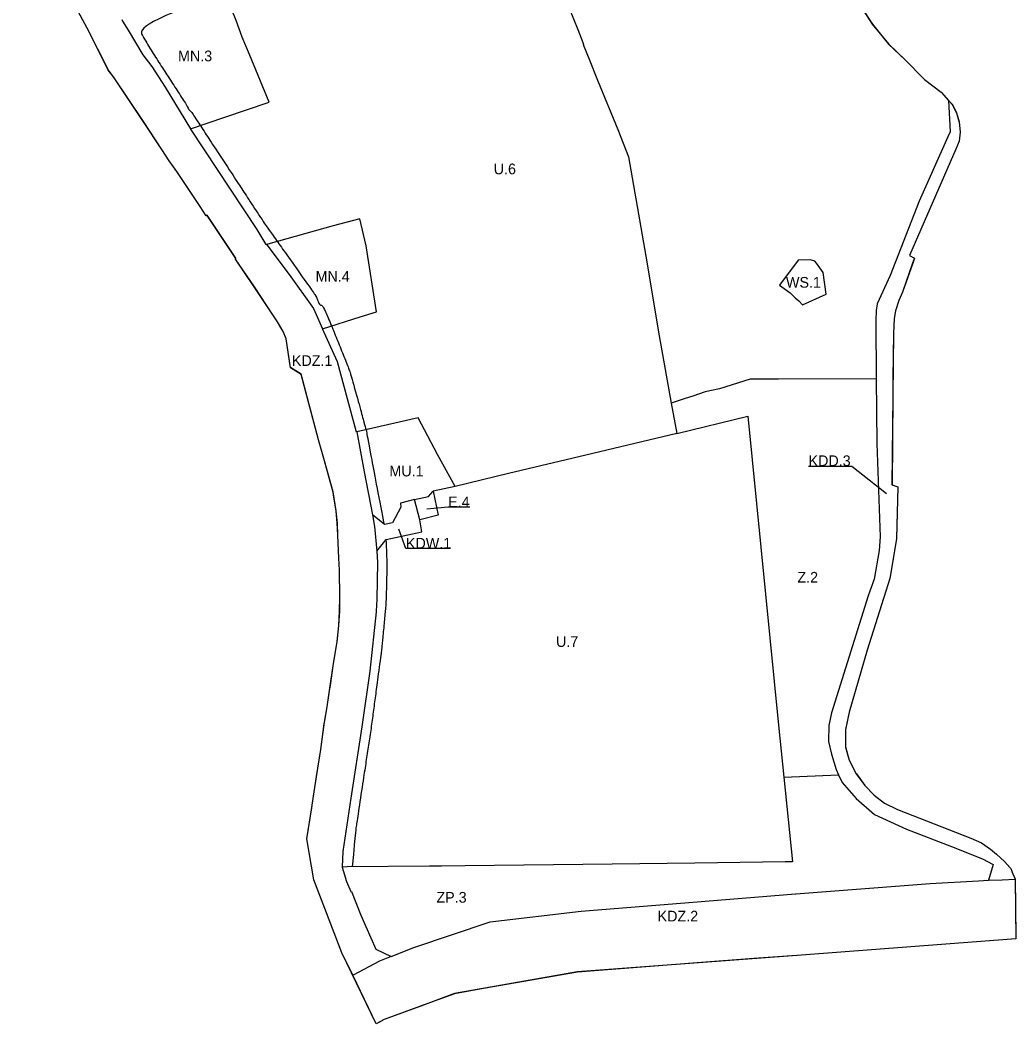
# Model space of a CAD drawing. Extents: x 7426917 to 7427860, y 5549047 to 5550050.
# Drawn here: x 7427266.6 to 7427685.5, y 5549047.4 to 5549469.9 of the extents above; entities that cross this region are included whole.
import ezdxf

# ---------------------------------------------------------------- set-up
doc = ezdxf.new("R2010")
doc.units = 0
for name, color, linetype in [('UG_WSCH_granica obszaru objętego planem', 7, 'Continuous'), ('UG_WSCH_linie rozgraniczające tereny', 7, 'Continuous'), ('UG_WSCH_linie rozgraniczające tereny_OPISY', 7, 'Continuous'), ('UG_WSCH_nieprzekraczalne linie zabudowy', 7, 'Continuous')]:
    doc.layers.add(name, color=color, linetype=linetype)

msp = doc.modelspace()

# ---------------------------------------------------------------- linework, layer by layer
at = {"layer": 'UG_WSCH_granica obszaru objętego planem'}
for p, q in [((7427303.71, 5549448.83), (7427294.86, 5549466.52)), ((7427305.89, 5549446.11), (7427303.71, 5549448.83)), ((7427318.5, 5549427.19), (7427305.89, 5549446.11)), ((7427326.25, 5549415.45), (7427318.5, 5549427.19)), ((7427329.32, 5549410.72), (7427326.25, 5549415.45)), ((7427331.18, 5549408.21), (7427329.32, 5549410.72)), ((7427344.92, 5549387.57), (7427342.4, 5549391.44)), ((7427357.25, 5549369.27), (7427357.31, 5549369.67)), ((7427365.12, 5549357.73), (7427357.25, 5549369.27)), ((7427374.86, 5549342.9), (7427365.12, 5549357.73)), ((7427380.29, 5549323.65), (7427378.49, 5549335.83)), ((7427394.66, 5549284.38), (7427392.05, 5549293.25)), ((7427398.23, 5549271.32), (7427394.66, 5549284.38)), ((7427399.55, 5549263.32), (7427398.23, 5549271.32)), ((7427401.02, 5549227.11), (7427400.89, 5549238.44)), ((7427401.01, 5549221.15), (7427401.02, 5549227.11)), ((7427400.6, 5549215.14), (7427401.01, 5549221.15)), ((7427399.97, 5549208.33), (7427400.6, 5549215.14)), ((7427398.44, 5549199.1), (7427399.97, 5549208.33)), ((7427396.79, 5549187.73), (7427398.44, 5549199.1)), ((7427395.7, 5549180.89), (7427396.79, 5549187.73)), ((7427394.65, 5549174.39), (7427395.7, 5549180.89)), ((7427393.05, 5549162.97), (7427394.65, 5549174.39)), ((7427391.32, 5549151.5), (7427393.05, 5549162.97)), ((7427390.28, 5549145.09), (7427391.32, 5549151.5)), ((7427389.3, 5549138.45), (7427390.28, 5549145.09)), ((7427387.18, 5549125.33), (7427389.3, 5549138.45)), ((7427630.13, 5549140.33), (7427635.71, 5549137.71)), ((7427390.15, 5549108.13), (7427387.18, 5549125.33)), ((7427683.29, 5549112.82), (7427684.22, 5549110.61)), ((7427401.94, 5549077.31), (7427390.15, 5549108.13)), ((7427684.22, 5549110.61), (7427685.15, 5549108.41)), ((7427685.15, 5549108.41), (7427685.45, 5549083.26)), ((7427685.45, 5549083.26), (7427595.26, 5549076.42)), ((7427416.4, 5549047.44), (7427401.94, 5549077.31)), ((7427595.26, 5549076.42), (7427501.08, 5549069.29)), ((7427439.22, 5549056.45), (7427419.77, 5549049.32)), ((7427419.77, 5549049.32), (7427416.4, 5549047.44))]:
    msp.add_line(p, q, dxfattribs=at)
for points in [[(7427294.86, 5549466.52), (7427282.38, 5549489.77), (7427278.39, 5549499.07), (7427266.6, 5549528.2)], [(7427620.19, 5549475.66), (7427625.06, 5549468.24), (7427631.86, 5549459.88), (7427638.82, 5549453.22), (7427647.03, 5549444.9), (7427654.02, 5549439.6), (7427658.71, 5549434.38), (7427660.48, 5549430.85), (7427661.64, 5549427.04), (7427662.02, 5549422.78), (7427661.56, 5549418.94), (7427660.19, 5549415.6), (7427640.63, 5549370.91), (7427642.77, 5549369.72), (7427642.02, 5549367.59), (7427637.71, 5549355.45), (7427636.16, 5549351.94), (7427634.78, 5549347.6), (7427634.26, 5549344.27), (7427633.98, 5549338.16), (7427633.63, 5549311.85), (7427633.33, 5549274.36), (7427635.77, 5549273.51), (7427635.25, 5549251.68), (7427632.43, 5549234.9), (7427622.9, 5549204.73), (7427615.37, 5549178.61), (7427613.76, 5549171.29), (7427613.73, 5549163.98), (7427615.29, 5549158.39), (7427618.32, 5549152.71)], [(7427342.4, 5549391.44), (7427332.51, 5549406.21), (7427331.18, 5549408.21)], [(7427357.31, 5549369.67), (7427345.31, 5549387.76), (7427344.92, 5549387.57)], [(7427378.49, 5549335.83), (7427377.23, 5549338.89), (7427374.86, 5549342.9)], [(7427392.05, 5549293.25), (7427384.84, 5549320.85), (7427380.29, 5549323.65)], [(7427400.26, 5549253.11), (7427400.03, 5549258.25), (7427399.55, 5549263.32)], [(7427400.89, 5549238.44), (7427400.69, 5549243.41), (7427400.26, 5549253.11)], [(7427618.32, 5549152.71), (7427618.33, 5549152.68), (7427621.89, 5549147.82)], [(7427621.89, 5549147.82), (7427625.79, 5549143.76), (7427630.13, 5549140.33)], [(7427635.71, 5549137.71), (7427666.46, 5549125.62), (7427670.99, 5549123.63), (7427674.8, 5549120.98), (7427677.28, 5549118.83)], [(7427677.28, 5549118.83), (7427680.71, 5549115.84), (7427682.96, 5549113.2), (7427683.29, 5549112.82)], [(7427501.08, 5549069.29), (7427449.35, 5549060.17), (7427439.22, 5549056.45)]]:
    msp.add_lwpolyline(points, dxfattribs=at)
at = {"layer": 'UG_WSCH_linie rozgraniczające tereny'}
for p, q in [((7427491.55, 5549489.75), (7427501.17, 5549466.02)), ((7427357.45, 5549469.81), (7427352.93, 5549480.99)), ((7427620.2, 5549475.64), (7427625.07, 5549468.22)), ((7427294.87, 5549466.5), (7427291.21, 5549473.32)), ((7427309.36, 5549470.22), (7427309.73, 5549469.5)), ((7427303.72, 5549448.81), (7427294.87, 5549466.5)), ((7427309.73, 5549469.5), (7427312.06, 5549465.72)), ((7427359.99, 5549462.68), (7427357.45, 5549469.81)), ((7427501.17, 5549466.02), (7427503.27, 5549460.48)), ((7427625.07, 5549468.22), (7427631.87, 5549459.86)), ((7427312.06, 5549465.72), (7427318.17, 5549455.26)), ((7427363.06, 5549455.42), (7427359.99, 5549462.68)), ((7427503.27, 5549460.48), (7427503.74, 5549458.92)), ((7427503.74, 5549458.92), (7427505.92, 5549453.42)), ((7427631.87, 5549459.86), (7427638.83, 5549453.2)), ((7427318.17, 5549455.26), (7427321.99, 5549450.34)), ((7427371.43, 5549435.45), (7427363.06, 5549455.42)), ((7427505.92, 5549453.42), (7427509.4, 5549444.66)), ((7427638.83, 5549453.2), (7427647.04, 5549444.88)), ((7427321.99, 5549450.34), (7427327.56, 5549441.64)), ((7427305.9, 5549446.09), (7427303.72, 5549448.81)), ((7427318.51, 5549427.17), (7427305.9, 5549446.09)), ((7427647.04, 5549444.88), (7427654.03, 5549439.58)), ((7427327.56, 5549441.64), (7427338.33, 5549424.18)), ((7427509.4, 5549444.66), (7427517.96, 5549423.9)), ((7427654.03, 5549439.58), (7427657.12, 5549436.13)), ((7427352.71, 5549429.08), (7427371.43, 5549435.45)), ((7427657.12, 5549436.13), (7427657.83, 5549422.96)), ((7427657.12, 5549436.13), (7427658.72, 5549434.36)), ((7427658.72, 5549434.36), (7427660.49, 5549430.83)), ((7427338.33, 5549424.18), (7427352.71, 5549429.08)), ((7427660.49, 5549430.83), (7427660.8, 5549429.8)), ((7427660.8, 5549429.8), (7427661.65, 5549427.02)), ((7427326.26, 5549415.43), (7427318.51, 5549427.17)), ((7427338.24, 5549424.15), (7427338.33, 5549424.18)), ((7427338.36, 5549424.06), (7427338.24, 5549424.15)), ((7427366.25, 5549381.84), (7427338.36, 5549424.06)), ((7427517.96, 5549423.9), (7427522.47, 5549412.39)), ((7427661.65, 5549427.02), (7427662.03, 5549422.76)), ((7427656.88, 5549420.77), (7427644.74, 5549393.72)), ((7427657.83, 5549422.96), (7427656.88, 5549420.77)), ((7427662.03, 5549422.76), (7427661.57, 5549418.92)), ((7427329.33, 5549410.7), (7427326.26, 5549415.43)), ((7427660.2, 5549415.58), (7427640.64, 5549370.89)), ((7427661.57, 5549418.92), (7427660.2, 5549415.58)), ((7427522.47, 5549412.39), (7427529.73, 5549370.56)), ((7427331.19, 5549408.19), (7427329.33, 5549410.7)), ((7427332.52, 5549406.19), (7427331.19, 5549408.19)), ((7427342.41, 5549391.42), (7427332.52, 5549406.19)), ((7427344.93, 5549387.55), (7427342.41, 5549391.42)), ((7427644.74, 5549393.72), (7427632.59, 5549362.39)), ((7427345.21, 5549387.69), (7427344.93, 5549387.55)), ((7427345.32, 5549387.74), (7427345.21, 5549387.69)), ((7427349.49, 5549381.44), (7427345.32, 5549387.74)), ((7427409.45, 5549386.34), (7427398.33, 5549383.28)), ((7427412.12, 5549374.85), (7427409.45, 5549386.34)), ((7427357.32, 5549369.65), (7427349.49, 5549381.44)), ((7427370.12, 5549375.46), (7427366.25, 5549381.84)), ((7427398.33, 5549383.28), (7427370.78, 5549375.67)), ((7427370.21, 5549375.32), (7427370.12, 5549375.46)), ((7427370.34, 5549375.41), (7427370.21, 5549375.32)), ((7427370.78, 5549375.67), (7427370.34, 5549375.41)), ((7427370.34, 5549375.41), (7427370.36, 5549375.4)), ((7427370.36, 5549375.4), (7427379.78, 5549362.88)), ((7427416.54, 5549347.18), (7427412.12, 5549374.85)), ((7427357.26, 5549369.25), (7427357.32, 5549369.65)), ((7427365.13, 5549357.71), (7427357.26, 5549369.25)), ((7427529.73, 5549370.56), (7427535.38, 5549337.03)), ((7427593.89, 5549368.87), (7427586.03, 5549358.39)), ((7427599, 5549369.01), (7427593.89, 5549368.87)), ((7427600.88, 5549368.42), (7427599, 5549369.01)), ((7427640.64, 5549370.89), (7427642.78, 5549369.7)), ((7427642.78, 5549369.7), (7427642.03, 5549367.57)), ((7427601.57, 5549367.69), (7427600.88, 5549368.42)), ((7427604.32, 5549363.75), (7427601.57, 5549367.69)), ((7427642.03, 5549367.57), (7427637.72, 5549355.43)), ((7427379.78, 5549362.88), (7427389.97, 5549348.56)), ((7427605.65, 5549354.51), (7427604.32, 5549363.75)), ((7427632.59, 5549362.39), (7427627.07, 5549350.52)), ((7427372.58, 5549346.36), (7427365.13, 5549357.71)), ((7427586.03, 5549358.39), (7427590.5, 5549355.15)), ((7427590.5, 5549355.15), (7427592.66, 5549353.1)), ((7427592.66, 5549353.1), (7427594.09, 5549351.75)), ((7427594.09, 5549351.75), (7427595.76, 5549350.08)), ((7427595.76, 5549350.08), (7427605.65, 5549354.51)), ((7427636.17, 5549351.92), (7427634.79, 5549347.58)), ((7427637.72, 5549355.43), (7427636.17, 5549351.92)), ((7427389.97, 5549348.56), (7427393.83, 5549340.01)), ((7427626.66, 5549347.76), (7427626.52, 5549343.48)), ((7427627.07, 5549350.52), (7427626.66, 5549347.76)), ((7427634.79, 5549347.58), (7427634.27, 5549344.25)), ((7427374.87, 5549342.88), (7427372.58, 5549346.36)), ((7427393.83, 5549340.01), (7427409.71, 5549345.03)), ((7427409.71, 5549345.03), (7427416.54, 5549347.18)), ((7427626.52, 5549343.48), (7427626.72, 5549318.89)), ((7427634.27, 5549344.25), (7427633.99, 5549338.14)), ((7427375.73, 5549341.43), (7427374.87, 5549342.88)), ((7427377.24, 5549338.87), (7427375.73, 5549341.43)), ((7427400.08, 5549326.1), (7427393.83, 5549340.01)), ((7427378.5, 5549335.81), (7427377.24, 5549338.87)), ((7427380.3, 5549323.63), (7427378.5, 5549335.81)), ((7427535.38, 5549337.03), (7427540.47, 5549308.7)), ((7427633.99, 5549338.14), (7427633.73, 5549319.02)), ((7427384.85, 5549320.83), (7427380.3, 5549323.63)), ((7427408.1, 5549296.55), (7427400.08, 5549326.1)), ((7427392.06, 5549293.23), (7427384.85, 5549320.83)), ((7427573.62, 5549318.75), (7427560.77, 5549314.76)), ((7427581.7, 5549318.77), (7427573.62, 5549318.75)), ((7427585.61, 5549318.78), (7427581.7, 5549318.77)), ((7427626.72, 5549318.89), (7427585.61, 5549318.78)), ((7427626.72, 5549318.89), (7427626.94, 5549291.73)), ((7427633.73, 5549318.91), (7427633.64, 5549311.83)), ((7427633.73, 5549319.02), (7427633.73, 5549318.91)), ((7427560.77, 5549314.76), (7427554.8, 5549313.42)), ((7427546.33, 5549310.64), (7427540.47, 5549308.7)), ((7427549.57, 5549311.7), (7427546.33, 5549310.64)), ((7427554.8, 5549313.42), (7427549.57, 5549311.7)), ((7427633.64, 5549311.83), (7427633.34, 5549274.34)), ((7427540.47, 5549308.7), (7427542.77, 5549295.97)), ((7427434.05, 5549302.53), (7427408.23, 5549296.58)), ((7427442.2, 5549287.1), (7427434.05, 5549302.53)), ((7427542.77, 5549295.97), (7427572.63, 5549303.22)), ((7427572.63, 5549303.22), (7427585.65, 5549173.18)), ((7427394.67, 5549284.36), (7427392.06, 5549293.23)), ((7427408.23, 5549296.58), (7427408.1, 5549296.55)), ((7427408.23, 5549296.58), (7427411.35, 5549279.78)), ((7427542.77, 5549295.97), (7427504.51, 5549286.84)), ((7427626.94, 5549291.73), (7427628.32, 5549252.4)), ((7427397.01, 5549275.78), (7427394.67, 5549284.36)), ((7427449.53, 5549273.67), (7427442.2, 5549287.1)), ((7427504.51, 5549286.84), (7427472.08, 5549279.11)), ((7427398.24, 5549271.3), (7427397.01, 5549275.78)), ((7427411.35, 5549279.78), (7427414.76, 5549261.73)), ((7427472.08, 5549279.11), (7427449.53, 5549273.67)), ((7427438.42, 5549269.45), (7427440.37, 5549271.69)), ((7427449.53, 5549273.67), (7427440.37, 5549271.69)), ((7427440.37, 5549271.69), (7427442.39, 5549261.5)), ((7427633.34, 5549274.34), (7427635.78, 5549273.49)), ((7427635.78, 5549273.49), (7427635.26, 5549251.66)), ((7427398.6, 5549269.12), (7427398.24, 5549271.3)), ((7427399.56, 5549263.3), (7427398.6, 5549269.12)), ((7427432.46, 5549268.09), (7427426.54, 5549266.59)), ((7427432.46, 5549268.09), (7427438.42, 5549269.45)), ((7427434.67, 5549259.59), (7427432.46, 5549268.09)), ((7427400.04, 5549258.23), (7427399.56, 5549263.3)), ((7427426.81, 5549264.93), (7427423.25, 5549258.31)), ((7427426.54, 5549266.59), (7427426.81, 5549264.93)), ((7427414.76, 5549261.73), (7427415.68, 5549256.82)), ((7427419.91, 5549257.65), (7427414.76, 5549261.73)), ((7427442.39, 5549261.5), (7427434.67, 5549259.59)), ((7427435.52, 5549254.6), (7427434.67, 5549259.59)), ((7427400.27, 5549253.09), (7427400.04, 5549258.23)), ((7427415.68, 5549256.82), (7427416.71, 5549246.45)), ((7427423.25, 5549258.31), (7427419.91, 5549257.65)), ((7427420.51, 5549251.37), (7427435.52, 5549254.6)), ((7427400.7, 5549243.39), (7427400.27, 5549253.09)), ((7427416.71, 5549246.45), (7427420.51, 5549251.37)), ((7427628.32, 5549252.4), (7427627.9, 5549246.74)), ((7427635.26, 5549251.66), (7427632.44, 5549234.88)), ((7427416.71, 5549246.45), (7427416.94, 5549241.61)), ((7427627.9, 5549246.74), (7427625.83, 5549234.6)), ((7427400.9, 5549238.42), (7427400.7, 5549243.39)), ((7427401.03, 5549227.09), (7427400.9, 5549238.42)), ((7427416.94, 5549241.61), (7427416.6, 5549226.25)), ((7427632.44, 5549234.88), (7427622.91, 5549204.71)), ((7427625.83, 5549234.6), (7427623.35, 5549227.56)), ((7427401.02, 5549221.13), (7427401.03, 5549227.09)), ((7427416.6, 5549226.25), (7427416.34, 5549221.15)), ((7427623.35, 5549227.56), (7427607.89, 5549178.29)), ((7427400.61, 5549215.12), (7427401.02, 5549221.13)), ((7427416.38, 5549220.83), (7427413.64, 5549195.96)), ((7427416.34, 5549221.15), (7427416.38, 5549220.83)), ((7427399.98, 5549208.31), (7427400.61, 5549215.12)), ((7427398.45, 5549199.08), (7427399.98, 5549208.31)), ((7427622.91, 5549204.71), (7427615.38, 5549178.59)), ((7427397.11, 5549189.88), (7427398.45, 5549199.08)), ((7427413.64, 5549195.96), (7427410.28, 5549172.43)), ((7427396.63, 5549186.65), (7427396.8, 5549187.71)), ((7427396.8, 5549187.71), (7427397.11, 5549189.88)), ((7427395.71, 5549180.87), (7427396.63, 5549186.65)), ((7427394.75, 5549174.94), (7427395.71, 5549180.87)), ((7427615.38, 5549178.59), (7427613.77, 5549171.27)), ((7427394.56, 5549173.68), (7427394.66, 5549174.37)), ((7427394.66, 5549174.37), (7427394.75, 5549174.94)), ((7427607.89, 5549178.29), (7427606.79, 5549173.05)), ((7427393.06, 5549162.95), (7427394.56, 5549173.68)), ((7427410.28, 5549172.43), (7427405.69, 5549142.41)), ((7427585.65, 5549173.18), (7427587.85, 5549151.3)), ((7427606.79, 5549173.05), (7427606.65, 5549166.29)), ((7427613.77, 5549171.27), (7427613.74, 5549163.96)), ((7427606.65, 5549166.29), (7427607.89, 5549160.91)), ((7427391.33, 5549151.48), (7427393.06, 5549162.95)), ((7427613.74, 5549163.96), (7427615.3, 5549158.37)), ((7427607.89, 5549160.91), (7427609.82, 5549154.56)), ((7427615.3, 5549158.37), (7427618.33, 5549152.69)), ((7427609.82, 5549154.56), (7427610.83, 5549152.33)), ((7427390.29, 5549145.07), (7427391.33, 5549151.48)), ((7427587.85, 5549151.3), (7427587.91, 5549151.31)), ((7427587.85, 5549151.3), (7427591.43, 5549115.63)), ((7427587.91, 5549151.31), (7427610.83, 5549152.33)), ((7427610.83, 5549152.33), (7427612.31, 5549149.04)), ((7427612.31, 5549149.04), (7427618.24, 5549142.28)), ((7427618.33, 5549152.69), (7427618.34, 5549152.66)), ((7427618.34, 5549152.66), (7427621.9, 5549147.8)), ((7427389.61, 5549140.51), (7427390.29, 5549145.07)), ((7427621.9, 5549147.8), (7427625.8, 5549143.74)), ((7427389.31, 5549138.43), (7427389.61, 5549140.51)), ((7427405.69, 5549142.41), (7427402.32, 5549119.97)), ((7427618.24, 5549142.28), (7427625.97, 5549135.51)), ((7427625.8, 5549143.74), (7427630.14, 5549140.31)), ((7427387.19, 5549125.35), (7427389.31, 5549138.43)), ((7427630.14, 5549140.31), (7427635.72, 5549137.69)), ((7427635.72, 5549137.69), (7427666.47, 5549125.6)), ((7427625.97, 5549135.51), (7427639.5, 5549129.44)), ((7427639.5, 5549129.44), (7427658.4, 5549122.13)), ((7427387.19, 5549125.31), (7427387.19, 5549125.35)), ((7427390.16, 5549108.11), (7427387.19, 5549125.31)), ((7427666.47, 5549125.6), (7427671, 5549123.61)), ((7427671, 5549123.61), (7427674.81, 5549120.96)), ((7427402.32, 5549119.97), (7427402.12, 5549113.48)), ((7427658.4, 5549122.13), (7427671.37, 5549116.88)), ((7427674.81, 5549120.96), (7427677.29, 5549118.81)), ((7427588.44, 5549115.62), (7427550.44, 5549115.04)), ((7427591.43, 5549115.63), (7427588.44, 5549115.62)), ((7427671.37, 5549116.88), (7427675.93, 5549114.5)), ((7427677.29, 5549118.81), (7427680.72, 5549115.82)), ((7427680.72, 5549115.82), (7427682.97, 5549113.18)), ((7427402.12, 5549113.48), (7427402.13, 5549113.45)), ((7427404.23, 5549113.5), (7427402.13, 5549113.45)), ((7427402.13, 5549113.45), (7427403.86, 5549107.34)), ((7427438.79, 5549113.82), (7427404.23, 5549113.5)), ((7427443.79, 5549113.88), (7427438.79, 5549113.82)), ((7427453.79, 5549113.98), (7427443.79, 5549113.88)), ((7427515.66, 5549114.61), (7427453.79, 5549113.98)), ((7427550.44, 5549115.04), (7427515.66, 5549114.61)), ((7427675.93, 5549114.5), (7427673.99, 5549107.88)), ((7427682.97, 5549113.18), (7427683.3, 5549112.8)), ((7427683.3, 5549112.8), (7427683.75, 5549111.71)), ((7427683.75, 5549111.71), (7427683.76, 5549111.71)), ((7427683.76, 5549111.71), (7427683.76, 5549111.7)), ((7427683.76, 5549111.7), (7427683.76, 5549111.69)), ((7427683.76, 5549111.69), (7427683.76, 5549111.69)), ((7427683.76, 5549111.69), (7427683.77, 5549111.68)), ((7427683.77, 5549111.68), (7427683.77, 5549111.68)), ((7427683.77, 5549111.68), (7427683.77, 5549111.67)), ((7427683.77, 5549111.67), (7427683.77, 5549111.67)), ((7427683.77, 5549111.67), (7427683.78, 5549111.66)), ((7427683.78, 5549111.66), (7427683.78, 5549111.66)), ((7427683.78, 5549111.66), (7427683.78, 5549111.65)), ((7427683.78, 5549111.65), (7427683.78, 5549111.65)), ((7427683.78, 5549111.65), (7427683.78, 5549111.65)), ((7427683.78, 5549111.65), (7427683.78, 5549111.64)), ((7427683.78, 5549111.64), (7427683.78, 5549111.64)), ((7427683.78, 5549111.64), (7427683.79, 5549111.64)), ((7427683.79, 5549111.64), (7427683.79, 5549111.63)), ((7427683.79, 5549111.63), (7427683.79, 5549111.63)), ((7427683.79, 5549111.63), (7427683.79, 5549111.63)), ((7427683.79, 5549111.63), (7427683.79, 5549111.62)), ((7427683.79, 5549111.62), (7427684.23, 5549110.59)), ((7427401.95, 5549077.29), (7427390.16, 5549108.11)), ((7427403.86, 5549107.34), (7427405.69, 5549103.1)), ((7427649.33, 5549106.58), (7427669.75, 5549107.68)), ((7427669.75, 5549107.68), (7427673.99, 5549107.88)), ((7427673.99, 5549107.88), (7427679.65, 5549108.14)), ((7427679.65, 5549108.14), (7427685.16, 5549108.39)), ((7427684.23, 5549110.59), (7427684.7, 5549109.48)), ((7427684.7, 5549109.48), (7427685.16, 5549108.39)), ((7427685.16, 5549108.39), (7427685.16, 5549107.76)), ((7427685.16, 5549107.76), (7427685.28, 5549097.58)), ((7427405.69, 5549103.1), (7427405.99, 5549103.1)), ((7427405.99, 5549103.1), (7427409.96, 5549093.24)), ((7427592.87, 5549102.19), (7427649.33, 5549106.58)), ((7427542.74, 5549098.1), (7427592.78, 5549102.19)), ((7427592.78, 5549102.19), (7427592.87, 5549102.19)), ((7427464.34, 5549090.44), (7427502.56, 5549094.82)), ((7427502.56, 5549094.82), (7427542.74, 5549098.1)), ((7427685.28, 5549097.58), (7427685.46, 5549083.24)), ((7427409.96, 5549093.24), (7427416.17, 5549078.85)), ((7427432.2, 5549079.54), (7427464.34, 5549090.44)), ((7427685.46, 5549083.24), (7427595.27, 5549076.4)), ((7427406.49, 5549067.91), (7427401.95, 5549077.29)), ((7427416.17, 5549078.85), (7427422.67, 5549075.74)), ((7427422.67, 5549075.74), (7427432.2, 5549079.54)), ((7427417.82, 5549073.81), (7427406.64, 5549067.97)), ((7427422.67, 5549075.74), (7427417.82, 5549073.81)), ((7427551.44, 5549073.09), (7427501.09, 5549069.27)), ((7427575.28, 5549074.89), (7427551.44, 5549073.09)), ((7427595.27, 5549076.4), (7427575.28, 5549074.89)), ((7427501.09, 5549069.27), (7427461.49, 5549062.29)), ((7427406.64, 5549067.97), (7427406.49, 5549067.91)), ((7427416.41, 5549047.42), (7427406.49, 5549067.91)), ((7427461.49, 5549062.29), (7427449.36, 5549060.15)), ((7427439.23, 5549056.43), (7427435.12, 5549054.93)), ((7427449.36, 5549060.15), (7427439.23, 5549056.43)), ((7427435.12, 5549054.93), (7427419.78, 5549049.3)), ((7427417.47, 5549048.02), (7427416.41, 5549047.42)), ((7427419.78, 5549049.3), (7427417.47, 5549048.02))]:
    msp.add_line(p, q, dxfattribs=at)
at = {"layer": 'UG_WSCH_linie rozgraniczające tereny_OPISY'}
for points in [[(7427598.23, 5549282.22), (7427616.47, 5549282.22), (7427631.05, 5549270.61)], [(7427455.77, 5549264.87), (7427446.64, 5549264.87), (7427437.66, 5549264.08)], [(7427447.65, 5549247.5), (7427428.89, 5549247.5), (7427425.91, 5549255.67)]]:
    msp.add_lwpolyline(points, dxfattribs=at)
at = {"layer": 'UG_WSCH_nieprzekraczalne linie zabudowy'}
for points in [[(7427352.71, 5549481.54), (7427315.45, 5549468.03), (7427318.19, 5549463.21), (7427321.58, 5549457.37), (7427325.53, 5549451.29), (7427329.34, 5549445.42), (7427333.15, 5549439.55), (7427336.91, 5549433.75), (7427337.72, 5549431.76), (7427338.17, 5549431.96), (7427339.35, 5549430.15), (7427340.61, 5549428.23), (7427344.45, 5549422.38), (7427348.29, 5549416.53), (7427355.97, 5549404.82), (7427359.81, 5549398.97), (7427363.64, 5549393.11), (7427369.54, 5549384.12), (7427371.42, 5549381.47), (7427375.47, 5549375.76), (7427379.52, 5549370.05), (7427387.62, 5549358.64), (7427391.12, 5549353.71), (7427391.45, 5549352.81), (7427392.57, 5549349.84), (7427393.64, 5549350.16), (7427394.75, 5549347.7), (7427397.5, 5549341.59), (7427400.21, 5549334.81), (7427402.81, 5549328.31), (7427405.36, 5549321.93), (7427405.39, 5549321.8), (7427409.13, 5549308.31), (7427411, 5549301.56), (7427412.13, 5549297.5), (7427412.13, 5549297.5), (7427413.67, 5549289.21), (7427417.09, 5549270.95), (7427419.6, 5549257.93)], [(7427420.44, 5549251.37), (7427420.7, 5549246.81), (7427420.91, 5549240.33), (7427420.75, 5549234.28), (7427420.5, 5549224.2), (7427420.13, 5549220.3), (7427419.46, 5549213.33), (7427418.79, 5549206.37), (7427418.71, 5549205.56), (7427416.97, 5549192.49), (7427416.05, 5549185.55), (7427415.13, 5549178.61), (7427414.23, 5549171.89), (7427413.15, 5549164.75), (7427412.09, 5549157.83), (7427411.04, 5549150.91), (7427408.94, 5549137.07), (7427407.89, 5549130.15), (7427407.75, 5549129.24), (7427406.3, 5549113.54)]]:
    msp.add_open_spline(points, degree=3, dxfattribs=at)

# ---------------------------------------------------------------- texts
at = {"layer": 'UG_WSCH_linie rozgraniczające tereny_OPISY'}
for s, p in [('MN.3', (7427333.02, 5549452.59)), ('U.6', (7427465.81, 5549405.04)), ('MN.4', (7427390.88, 5549359.82)), ('WS.1', (7427588.73, 5549357.31)), ('KDZ.1', (7427380.91, 5549324.35)), ('KDD.3', (7427598.23, 5549282.22)), ('MU.1', (7427421.94, 5549277.87)), ('E.4', (7427446.64, 5549264.87)), ('KDW.1', (7427428.89, 5549247.5)), ('Z.2', (7427593.55, 5549233.17)), ('U.7', (7427492.02, 5549206.11)), ('ZP.3', (7427441.7, 5549098.46)), ('KDZ.2', (7427534.74, 5549090.55))]:
    msp.add_text(s, height=4.5, dxfattribs=at).set_placement(p)

doc.saveas('drawing.dxf')
